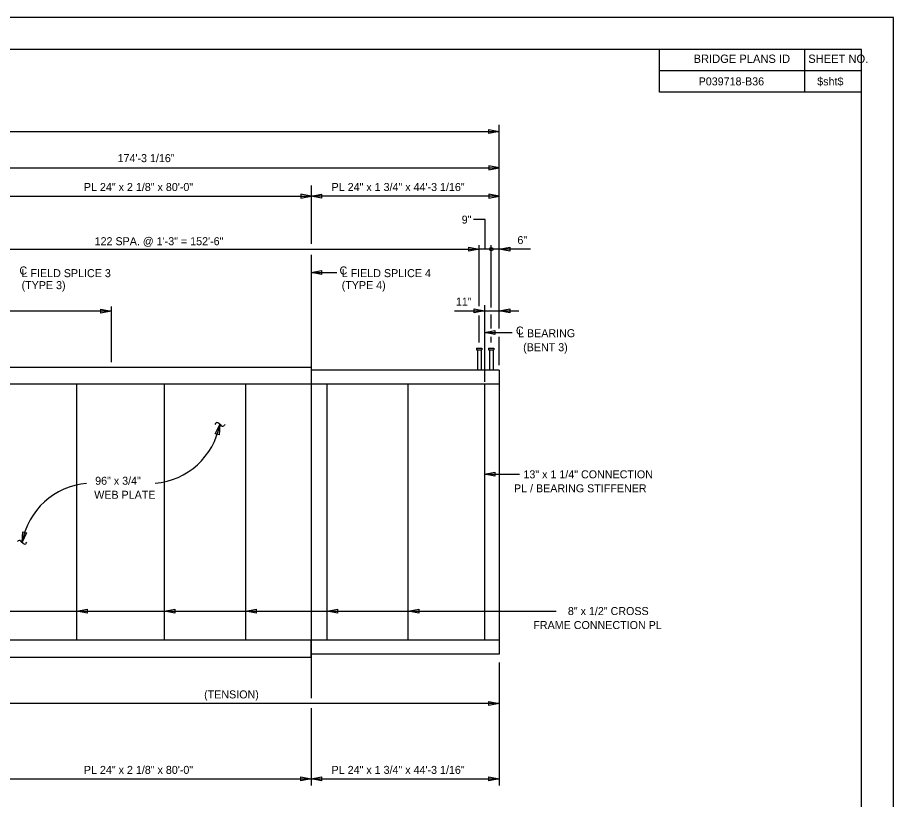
# Model space of a CAD drawing. Extents: x -305 to -161, y -187 to -99.
# Drawn here: x -215.9 to -161.2, y -148.4 to -99.5 of the extents above; entities that cross this region are included whole.
import ezdxf

# ---------------------------------------------------------------- set-up
doc = ezdxf.new("R2010")
doc.units = 0
for name, color, linetype in [('BR_AUTO DIMENSION', 7, 'Continuous'), ('BR_BORDER LINES', 7, 'Continuous'), ('BR_CENTER LINES', 7, 'Continuous'), ('BR_STRUCTURAL STEEL', 7, 'Continuous'), ('BR_TEXT', 7, 'Continuous'), ('Default', 7, 'Continuous'), ('Level 31', 7, 'Continuous')]:
    doc.layers.add(name, color=color, linetype=linetype)

msp = doc.modelspace()

# ---------------------------------------------------------------- linework, layer by layer
at = {"layer": 'BR_AUTO DIMENSION'}
for p, q in [((-284.516, -106.618), (-185.804, -106.618)), ((-185.804, -118.929), (-185.804, -106.206)), ((-230.055, -108.876), (-185.804, -108.876)), ((-217.555, -110.653), (-197.555, -110.653)), ((-185.804, -110.653), (-197.555, -110.653)), ((-187.054, -117.531), (-187.054, -113.71)), ((-186.304, -117.621), (-186.304, -113.71)), ((-224.929, -113.971), (-187.054, -113.971)), ((-183.851, -113.971), (-187.054, -113.971)), ((-197.555, -115.428), (-195.957, -115.428)), ((-210.055, -117.55), (-210.055, -121.025)), ((-210.055, -117.84), (-230.055, -117.84)), ((-188.605, -117.821), (-184.582, -117.821)), ((-187.054, -119.81), (-187.054, -118.105)), ((-186.304, -118.929), (-186.304, -118.048)), ((-186.721, -119.183), (-184.998, -119.183)), ((-186.304, -119.81), (-186.304, -119.447)), ((-185.804, -121.218), (-185.804, -119.447)), ((-186.721, -128.037), (-184.541, -128.037)), ((-220.077, -136.601), (-182.254, -136.601)), ((-185.804, -139.795), (-185.804, -147.486)), ((-185.804, -142.367), (-219.305, -142.367)), ((-217.555, -147.085), (-197.555, -147.085)), ((-197.555, -147.085), (-185.804, -147.085))]:
    msp.add_line(p, q, dxfattribs=at)
for points in [[(-186.454, -106.493), (-185.804, -106.618), (-186.454, -106.743)], [(-186.454, -109.001), (-185.804, -108.876), (-186.454, -108.751)], [(-198.205, -110.778), (-197.555, -110.653), (-198.205, -110.528)], [(-196.905, -110.778), (-197.555, -110.653), (-196.905, -110.528)], [(-186.454, -110.778), (-185.804, -110.653), (-186.454, -110.528)], [(-187.704, -113.846), (-187.054, -113.971), (-187.704, -114.096)], [(-185.154, -114.096), (-185.804, -113.971), (-185.154, -113.846)], [(-196.905, -115.553), (-197.555, -115.428), (-196.905, -115.303)], [(-210.705, -117.715), (-210.055, -117.84), (-210.705, -117.965)], [(-187.371, -117.696), (-186.721, -117.821), (-187.371, -117.946)], [(-185.154, -117.946), (-185.804, -117.821), (-185.154, -117.696)], [(-186.071, -119.308), (-186.721, -119.183), (-186.071, -119.058)], [(-203.547, -125.52), (-203.265, -124.922), (-203.305, -125.582)], [(-186.071, -128.162), (-186.721, -128.037), (-186.071, -127.912)], [(-215.333, -131.689), (-215.616, -132.287), (-215.576, -131.627)], [(-211.551, -136.726), (-212.201, -136.601), (-211.551, -136.476)], [(-206.074, -136.726), (-206.724, -136.601), (-206.074, -136.476)], [(-200.995, -136.726), (-201.645, -136.601), (-200.995, -136.476)], [(-195.916, -136.726), (-196.566, -136.601), (-195.916, -136.476)], [(-190.837, -136.726), (-191.487, -136.601), (-190.837, -136.476)], [(-186.454, -142.242), (-185.804, -142.367), (-186.454, -142.492)], [(-198.205, -146.96), (-197.555, -147.085), (-198.205, -147.21)], [(-196.905, -147.21), (-197.555, -147.085), (-196.905, -146.96)], [(-186.454, -146.96), (-185.804, -147.085), (-186.454, -147.21)]]:
    msp.add_lwpolyline(points, close=True, dxfattribs=at)
msp.add_lwpolyline([(-186.679, -113.971), (-186.679, -112.104), (-187.42, -112.104)], dxfattribs=at)
msp.add_circle((-186.304, -113.971), 0.111, dxfattribs=at)
for centre, start, end in [((-207.689, -124.118), 274.9624, 349.7037), ((-211.192, -133.091), 94.9624, 169.7037)]:
    msp.add_arc(centre, 4.497, start, end, dxfattribs=at)
at = {"layer": 'BR_BORDER LINES'}
for p, q in [((-163.178, -101.489), (-297.843, -101.489)), ((-175.788, -104.156), (-175.788, -101.489)), ((-166.722, -104.156), (-166.722, -101.489)), ((-163.178, -185.489), (-163.178, -101.489)), ((-175.788, -102.808), (-163.178, -102.808)), ((-166.722, -102.808), (-163.178, -102.808)), ((-163.178, -104.156), (-175.788, -104.156))]:
    msp.add_line(p, q, dxfattribs=at)
at = {"layer": 'BR_CENTER LINES'}
for p, q in [((-197.555, -109.997), (-197.555, -113.625)), ((-197.555, -114.323), (-197.555, -142.042)), ((-186.721, -117.463), (-186.721, -122.256)), ((-197.555, -142.667), (-197.555, -147.486))]:
    msp.add_line(p, q, dxfattribs=at)
at = {"layer": 'BR_STRUCTURAL STEEL'}
for p, q in [((-217.555, -121.35), (-197.555, -121.35)), ((-197.555, -121.35), (-197.555, -122.412)), ((-185.804, -121.537), (-197.555, -121.537)), ((-185.804, -121.537), (-185.804, -122.412)), ((-185.804, -122.412), (-284.516, -122.412)), ((-212.201, -138.412), (-212.201, -122.412)), ((-206.724, -138.412), (-206.724, -122.412)), ((-201.645, -138.412), (-201.645, -122.412)), ((-196.566, -138.412), (-196.566, -122.412)), ((-191.487, -138.412), (-191.487, -122.412)), ((-186.721, -122.412), (-186.721, -138.412)), ((-185.804, -122.412), (-185.804, -138.412)), ((-185.804, -138.412), (-284.516, -138.412)), ((-197.555, -139.475), (-197.555, -138.412)), ((-185.804, -138.412), (-185.804, -139.287)), ((-217.555, -139.475), (-197.555, -139.475)), ((-185.804, -139.287), (-197.555, -139.287))]:
    msp.add_line(p, q, dxfattribs=at)
at = {"layer": 'BR_TEXT'}
for p, q in [((-203.525, -124.869), (-203.567, -124.93)), ((-203.183, -124.996), (-203.346, -124.847)), ((-202.95, -124.93), (-202.979, -124.976)), ((-215.697, -132.213), (-215.534, -132.362)), ((-215.356, -132.34), (-215.314, -132.279))]:
    msp.add_line(p, q, dxfattribs=at)
for centre, radius, start, end in [((-203.427, -124.922), 0.111, 43.4519, 151.7375), ((-203.089, -124.915), 0.125, 221.007, 330.8059), ((-215.791, -132.294), 0.125, 41.007, 150.8059), ((-215.454, -132.287), 0.111, 223.4519, 331.7375)]:
    msp.add_arc(centre, radius, start, end, dxfattribs=at)
at = {"layer": 'Default'}
for p, q in [((-187.226, -120.162), (-187.226, -120.256)), ((-187.226, -120.162), (-186.883, -120.162)), ((-187.226, -120.256), (-186.883, -120.256)), ((-187.164, -120.256), (-187.164, -121.537)), ((-186.945, -120.256), (-186.945, -121.537)), ((-186.883, -120.162), (-186.883, -120.256)), ((-186.476, -120.162), (-186.476, -120.256)), ((-186.476, -120.162), (-186.133, -120.162)), ((-186.476, -120.256), (-186.133, -120.256)), ((-186.414, -120.256), (-186.414, -121.537)), ((-186.195, -120.256), (-186.195, -121.537)), ((-186.133, -120.162), (-186.133, -120.256))]:
    msp.add_line(p, q, dxfattribs=at)
at = {"layer": 'Level 31'}
msp.add_lwpolyline([(-305.176, -187.489), (-161.176, -187.489), (-161.176, -99.489), (-305.176, -99.489)], close=True, dxfattribs=at)

# ---------------------------------------------------------------- texts
at = {"layer": 'BR_AUTO DIMENSION'}
for s, p in [('174\'-3 1/16"', (-209.65, -108.53)), ('PL 24" x 2 1/8" x 80\'-0"', (-211.754, -110.334)), ('PL 24" x 1 3/4" x 44\'-3 1/16"', (-196.278, -110.334)), ('9"', (-188.151, -112.372)), ('6"', (-184.67, -113.652)), ('11"', (-188.514, -117.502)), ('96" x 3/4" ', (-211.05, -128.694)), ('WEB PLATE', (-211.109, -129.569)), ('(TENSION)', (-204.242, -142.048)), ('PL 24" x 2 1/8" x 80\'-0"', (-211.754, -146.766)), ('PL 24" x 1 3/4" x 44\'-3 1/16"', (-196.278, -146.766))]:
    msp.add_text(s, height=0.5, rotation=360, dxfattribs=at).set_placement(p)
msp.add_text('122 SPA. @ 1\'-3" = 152\'-6"', height=0.5, dxfattribs=at).set_placement((-211.082, -113.721))
at = {"layer": 'BR_TEXT'}
for s, height, p in [('BRIDGE PLANS ID', 0.52, (-173.663, -102.327)), ('SHEET NO.', 0.52, (-166.499, -102.327)), ('P039718-B36', 0.5, (-173.348, -103.732)), ('$sht$', 0.5, (-165.939, -103.732)), ('C', 0.5, (-184.763, -119.306)), ('L BEARING', 0.5, (-184.63, -119.473)), ('(BENT 3)', 0.5, (-184.312, -120.348)), ('13" x 1 1/4" CONNECTION ', 0.5, (-184.294, -128.293)), ('PL / BEARING STIFFENER', 0.5, (-184.886, -129.168)), ('8" x 1/2" CROSS ', 0.5, (-181.516, -136.838)), ('FRAME CONNECTION PL', 0.5, (-183.676, -137.713))]:
    msp.add_text(s, height=height, dxfattribs=at).set_placement(p)
for s, p in [('C', (-215.782, -115.551)), ('L FIELD SPLICE 3', (-215.647, -115.718)), ('C', (-195.782, -115.551)), ('L FIELD SPLICE 4', (-195.647, -115.718)), ('(TYPE 3)', (-215.647, -116.468)), ('(TYPE 4)', (-195.647, -116.468))]:
    msp.add_text(s, height=0.5, rotation=360, dxfattribs=at).set_placement(p)

doc.saveas('drawing.dxf')
